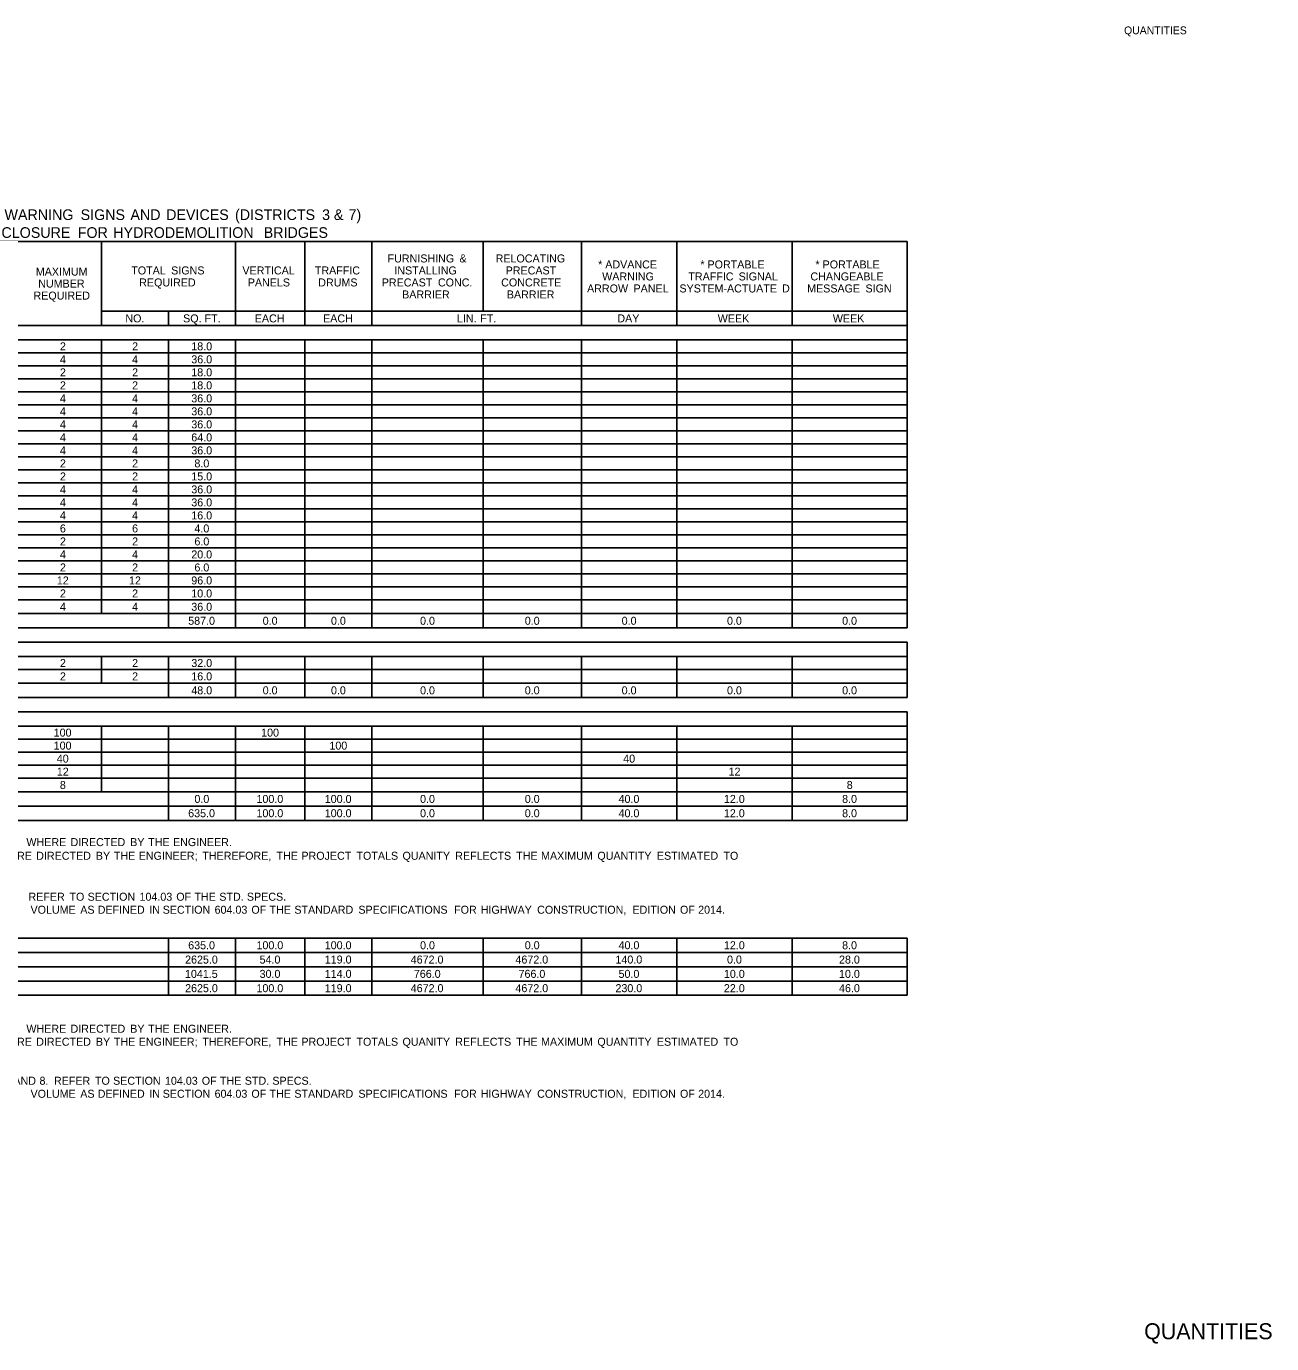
# Model space of a CAD drawing. Extents: x 540541 to 1930787, y -1948574 to 596640.
# Drawn here: x 544840 to 545774, y -1947044 to -1946056 of the extents above; entities that cross this region are included whole.
import ezdxf

# ---------------------------------------------------------------- set-up
doc = ezdxf.new("R2010")
doc.units = 0
for name, color, linetype in [('Default', 7, 'Continuous'), ('R_Border', 7, 'Continuous'), ('R_Border Prem', 7, 'Continuous')]:
    doc.layers.add(name, color=color, linetype=linetype)

msp = doc.modelspace()

# ---------------------------------------------------------------- linework, layer by layer
at = {"layer": 'Default'}
for p, q in [((544370.09, -1946217.86), (545500.6, -1946217.86)), ((544896.59, -1946280.75), (544896.59, -1946217.86)), ((544997.01, -1946280.75), (544997.01, -1946217.86)), ((545049.18, -1946280.75), (545049.18, -1946217.86)), ((545099.39, -1946280.75), (545099.39, -1946217.86)), ((545182.75, -1946270.02), (545182.75, -1946217.86)), ((545256.36, -1946280.75), (545256.36, -1946217.86)), ((545328.03, -1946280.75), (545328.03, -1946217.86)), ((545414.31, -1946280.75), (545414.31, -1946217.86)), ((545500.6, -1946270.02), (545500.6, -1946217.86)), ((544896.59, -1946270.02), (545500.6, -1946270.02)), ((544946.8, -1946280.75), (544946.8, -1946270.02)), ((545049.18, -1946280.75), (545049.18, -1946270.02)), ((545414.31, -1946280.75), (545414.31, -1946270.02)), ((545500.6, -1946291.47), (545500.6, -1946270.02)), ((544370.09, -1946280.75), (545500.6, -1946280.75)), ((544838.58, -1946280.75), (545500.6, -1946280.75)), ((544370.09, -1946291.47), (545500.6, -1946291.47)), ((544896.59, -1946496.71), (544896.59, -1946291.47)), ((544946.8, -1946496.71), (544946.8, -1946291.47)), ((544946.8, -1946507.44), (544946.8, -1946291.47)), ((544997.01, -1946507.44), (544997.01, -1946291.47)), ((544997.01, -1946507.44), (544997.01, -1946291.47)), ((545049.18, -1946486.47), (545049.18, -1946291.47)), ((545049.18, -1946507.44), (545049.18, -1946291.47)), ((545099.39, -1946507.44), (545099.39, -1946291.47)), ((545099.39, -1946507.44), (545099.39, -1946291.47)), ((545182.75, -1946507.44), (545182.75, -1946291.47)), ((545182.75, -1946507.44), (545182.75, -1946291.47)), ((545256.36, -1946507.44), (545256.36, -1946291.47)), ((545256.36, -1946507.44), (545256.36, -1946291.47)), ((545328.03, -1946507.44), (545328.03, -1946291.47)), ((545414.31, -1946507.44), (545414.31, -1946291.47)), ((545500.6, -1946496.71), (545500.6, -1946291.47)), ((544370.09, -1946301.22), (545500.6, -1946301.22)), ((544370.09, -1946310.97), (545500.6, -1946310.97)), ((544370.09, -1946320.72), (545500.6, -1946320.72)), ((544370.09, -1946330.47), (545500.6, -1946330.47)), ((544370.09, -1946340.22), (545500.6, -1946340.22)), ((544370.09, -1946349.97), (545500.6, -1946349.97)), ((544370.09, -1946359.72), (545500.6, -1946359.72)), ((544370.09, -1946369.47), (545500.6, -1946369.47)), ((544370.09, -1946379.22), (545500.6, -1946379.22)), ((544370.09, -1946388.97), (545500.6, -1946388.97)), ((544370.09, -1946398.72), (545500.6, -1946398.72)), ((544370.09, -1946408.47), (545500.6, -1946408.47)), ((544370.09, -1946418.22), (545500.6, -1946418.22)), ((544370.09, -1946427.97), (545500.6, -1946427.97)), ((544370.09, -1946437.72), (545500.6, -1946437.72)), ((544370.09, -1946447.47), (545500.6, -1946447.47)), ((544370.09, -1946457.22), (545500.6, -1946457.22)), ((544370.09, -1946466.97), (545500.6, -1946466.97)), ((544370.09, -1946476.72), (545500.6, -1946476.72)), ((544370.09, -1946486.47), (545500.6, -1946486.47)), ((544687.94, -1946496.71), (544997.01, -1946496.71)), ((544788.36, -1946496.71), (544997.01, -1946496.71)), ((544997.01, -1946496.71), (545049.18, -1946496.71)), ((545049.18, -1946496.71), (545500.6, -1946496.71)), ((545049.18, -1946507.44), (545049.18, -1946496.71)), ((545328.03, -1946507.44), (545328.03, -1946496.71)), ((545414.31, -1946507.44), (545414.31, -1946496.71)), ((545500.6, -1946507.44), (545500.6, -1946496.71)), ((544370.09, -1946507.44), (545500.6, -1946507.44)), ((544370.09, -1946518.16), (545500.6, -1946518.16)), ((544420.3, -1946518.16), (545500.6, -1946518.16)), ((545500.6, -1946528.89), (545500.6, -1946518.16)), ((544370.09, -1946528.89), (545500.6, -1946528.89)), ((544896.59, -1946548.87), (544896.59, -1946528.89)), ((544946.8, -1946548.87), (544946.8, -1946528.89)), ((544946.8, -1946559.6), (544946.8, -1946528.89)), ((544997.01, -1946548.87), (544997.01, -1946528.89)), ((544997.01, -1946559.6), (544997.01, -1946528.89)), ((545049.18, -1946559.6), (545049.18, -1946528.89)), ((545049.18, -1946559.6), (545049.18, -1946528.89)), ((545099.39, -1946559.6), (545099.39, -1946528.89)), ((545099.39, -1946559.6), (545099.39, -1946528.89)), ((545182.75, -1946559.6), (545182.75, -1946528.89)), ((545182.75, -1946559.6), (545182.75, -1946528.89)), ((545256.36, -1946559.6), (545256.36, -1946528.89)), ((545256.36, -1946559.6), (545256.36, -1946528.89)), ((545328.03, -1946559.6), (545328.03, -1946528.89)), ((545414.31, -1946559.6), (545414.31, -1946528.89)), ((545500.6, -1946559.6), (545500.6, -1946528.89)), ((544370.09, -1946538.64), (545500.6, -1946538.64)), ((544370.09, -1946548.87), (545500.6, -1946548.87)), ((544896.59, -1946548.87), (545500.6, -1946548.87)), ((545328.03, -1946559.6), (545328.03, -1946548.87)), ((544370.09, -1946559.6), (545500.6, -1946559.6)), ((544370.09, -1946570.32), (545500.6, -1946570.32)), ((545500.6, -1946651.74), (545500.6, -1946570.32)), ((544370.09, -1946581.05), (545500.6, -1946581.05)), ((544896.59, -1946630.29), (544896.59, -1946581.05)), ((544946.8, -1946651.74), (544946.8, -1946581.05)), ((544946.8, -1946651.74), (544946.8, -1946581.05)), ((544997.01, -1946651.74), (544997.01, -1946581.05)), ((544997.01, -1946651.74), (544997.01, -1946581.05)), ((545049.18, -1946651.74), (545049.18, -1946581.05)), ((545049.18, -1946651.74), (545049.18, -1946581.05)), ((545099.39, -1946651.74), (545099.39, -1946581.05)), ((545099.39, -1946651.74), (545099.39, -1946581.05)), ((545182.75, -1946651.74), (545182.75, -1946581.05)), ((545182.75, -1946651.74), (545182.75, -1946581.05)), ((545256.36, -1946651.74), (545256.36, -1946581.05)), ((545256.36, -1946651.74), (545256.36, -1946581.05)), ((545328.03, -1946651.74), (545328.03, -1946581.05)), ((545414.31, -1946651.74), (545414.31, -1946581.05)), ((544370.09, -1946590.8), (545500.6, -1946590.8)), ((544370.09, -1946600.55), (545500.6, -1946600.55)), ((544370.09, -1946610.3), (545500.6, -1946610.3)), ((544370.09, -1946620.05), (545500.6, -1946620.05)), ((544370.09, -1946630.29), (545414.31, -1946630.29)), ((544370.09, -1946630.29), (545500.6, -1946630.29)), ((545328.03, -1946651.74), (545328.03, -1946630.29)), ((545414.31, -1946630.29), (545500.6, -1946630.29)), ((544370.09, -1946641.01), (545500.6, -1946641.01)), ((544370.09, -1946651.74), (545500.6, -1946651.74)), ((544788.36, -1946739.97), (545500.6, -1946739.97)), ((544946.8, -1946739.97), (545500.6, -1946739.97)), ((544946.8, -1946782.87), (544946.8, -1946739.97)), ((544946.8, -1946782.87), (544946.8, -1946739.97)), ((544997.01, -1946782.87), (544997.01, -1946739.97)), ((545049.18, -1946772.15), (545049.18, -1946739.97)), ((545049.18, -1946782.87), (545049.18, -1946739.97)), ((545099.39, -1946750.7), (545099.39, -1946739.97)), ((545099.39, -1946782.87), (545099.39, -1946739.97)), ((545182.75, -1946750.7), (545182.75, -1946739.97)), ((545182.75, -1946782.87), (545182.75, -1946739.97)), ((545256.36, -1946750.7), (545256.36, -1946739.97)), ((545256.36, -1946782.87), (545256.36, -1946739.97)), ((545328.03, -1946750.7), (545328.03, -1946739.97)), ((545328.03, -1946782.87), (545328.03, -1946739.97)), ((545414.31, -1946782.87), (545414.31, -1946739.97)), ((545500.6, -1946782.87), (545500.6, -1946739.97)), ((544370.09, -1946750.7), (545500.6, -1946750.7)), ((544370.09, -1946761.42), (545500.6, -1946761.42)), ((544370.09, -1946772.15), (545500.6, -1946772.15)), ((544370.09, -1946782.87), (545500.6, -1946782.87))]:
    msp.add_line(p, q, dxfattribs=at)

# ---------------------------------------------------------------- texts
for s, height, p in [(' WARNING', 8, (544820.94, -1946201.63)), (' SIGNS', 8, (544878.01, -1946201.63)), (' AND', 8, (544915.35, -1946201.63)), (' DEVICES', 8, (544942.12, -1946201.63)), (' (DISTRICTS', 8, (544993.75, -1946201.63)), (' 3', 8, (545059.03, -1946201.63)), (' &', 8, (545067.86, -1946201.63)), (' 7)', 8, (545078.85, -1946201.63)), (' CLOSURE', 8, (544818.66, -1946215.04)), (' FOR', 8, (544875.86, -1946215.04)), (' HYDRODEMOLITION', 8, (544902.51, -1946215.04)), (' BRIDGES', 8, (545015.26, -1946215.04)), ('FURNISHING', 6, (545111.12, -1946233.44)), (' &', 6, (545162.78, -1946233.44)), ('RELOCATING', 6, (545192.1, -1946233.44)), ('*', 6, (545268.97, -1946237.94)), (' ADVANCE', 6, (545272.05, -1946237.94)), ('*', 6, (545345.61, -1946237.94)), (' PORTABLE', 6, (545348.7, -1946237.94)), ('*', 6, (545431.9, -1946237.94)), (' PORTABLE', 6, (545434.98, -1946237.94)), ('MAXIMUM', 6, (544847.39, -1946243.31)), ('TOTAL', 6, (544918.95, -1946242.44)), (' SIGNS', 6, (544946.64, -1946242.44)), ('VERTICAL', 6, (545002.26, -1946242.44)), ('TRAFFIC', 6, (545056.57, -1946242.44)), ('INSTALLING', 6, (545116.17, -1946242.44)), ('PRECAST', 6, (545199.61, -1946242.44)), ('WARNING', 6, (545271.96, -1946246.94)), ('TRAFFIC', 6, (545336.58, -1946246.94)), (' SIGNAL', 6, (545372.01, -1946246.94)), ('CHANGEABLE', 6, (545428.09, -1946246.94)), ('NUMBER', 6, (544849.2, -1946252.31)), ('REQUIRED', 6, (544924.88, -1946251.44)), ('PANELS', 6, (545006.29, -1946251.44)), ('DRUMS', 6, (545059.12, -1946251.44)), ('PRECAST', 6, (545106.74, -1946251.44)), (' CONC.', 6, (545146.63, -1946251.44)), ('CONCRETE', 6, (545196.24, -1946251.44)), ('ARROW', 6, (545260.65, -1946255.94)), (' PANEL', 6, (545293.24, -1946255.94)), ('SYSTEM-ACTUATE', 6, (545329.9, -1946255.94)), ('D', 6, (545406.8, -1946255.94)), ('MESSAGE', 6, (545425.62, -1946255.94)), (' SIGN', 6, (545467.14, -1946255.94)), ('REQUIRED', 6, (544845.66, -1946261.31)), ('BARRIER', 6, (545121.99, -1946260.44)), ('BARRIER', 6, (545200.48, -1946260.44)), ('NO.', 6, (544914.53, -1946278.39)), ('SQ.', 6, (544957.81, -1946278.39)), (' FT.', 6, (544971.68, -1946278.39)), ('EACH', 6, (545011.54, -1946278.39)), ('EACH', 6, (545062.73, -1946278.39)), ('LIN.', 6, (545163.09, -1946278.39)), (' FT.', 6, (545178.34, -1946278.39)), ('DAY', 6, (545283.34, -1946278.39)), ('WEEK', 6, (545358.6, -1946278.39)), ('WEEK', 6, (545444.89, -1946278.39)), ('2', 6, (544865.47, -1946299.35)), ('2', 6, (544919.59, -1946299.35)), ('18.0', 6, (544963.95, -1946299.35)), ('4', 6, (544865.46, -1946309.1)), ('4', 6, (544919.57, -1946309.1)), ('36.0', 6, (544963.95, -1946309.1)), ('2', 6, (544865.47, -1946318.85)), ('2', 6, (544919.59, -1946318.85)), ('18.0', 6, (544963.95, -1946318.85)), ('2', 6, (544865.47, -1946328.6)), ('2', 6, (544919.59, -1946328.6)), ('18.0', 6, (544963.95, -1946328.6)), ('4', 6, (544865.46, -1946338.35)), ('4', 6, (544919.57, -1946338.35)), ('36.0', 6, (544963.95, -1946338.35)), ('4', 6, (544865.46, -1946348.1)), ('4', 6, (544919.57, -1946348.1)), ('36.0', 6, (544963.95, -1946348.1)), ('4', 6, (544865.46, -1946357.85)), ('4', 6, (544919.57, -1946357.85)), ('36.0', 6, (544963.95, -1946357.85)), ('4', 6, (544865.46, -1946367.6)), ('4', 6, (544919.57, -1946367.6)), ('64.0', 6, (544963.95, -1946367.6)), ('4', 6, (544865.46, -1946377.35)), ('4', 6, (544919.57, -1946377.35)), ('36.0', 6, (544963.95, -1946377.35)), ('2', 6, (544865.47, -1946387.1)), ('2', 6, (544919.59, -1946387.1)), ('8.0', 6, (544966.28, -1946387.1)), ('2', 6, (544865.47, -1946396.85)), ('2', 6, (544919.59, -1946396.85)), ('15.0', 6, (544963.95, -1946396.85)), ('4', 6, (544865.46, -1946406.6)), ('4', 6, (544919.57, -1946406.6)), ('36.0', 6, (544963.95, -1946406.6)), ('4', 6, (544865.46, -1946416.35)), ('4', 6, (544919.57, -1946416.35)), ('36.0', 6, (544963.95, -1946416.35)), ('4', 6, (544865.46, -1946426.1)), ('4', 6, (544919.57, -1946426.1)), ('16.0', 6, (544963.95, -1946426.1)), ('6', 6, (544865.44, -1946435.85)), ('6', 6, (544919.55, -1946435.85)), ('4.0', 6, (544966.28, -1946435.85)), ('2', 6, (544865.47, -1946445.6)), ('2', 6, (544919.59, -1946445.6)), ('6.0', 6, (544966.28, -1946445.6)), ('4', 6, (544865.46, -1946455.35)), ('4', 6, (544919.57, -1946455.35)), ('20.0', 6, (544963.95, -1946455.35)), ('2', 6, (544865.47, -1946465.1)), ('2', 6, (544919.59, -1946465.1)), ('6.0', 6, (544966.28, -1946465.1)), ('12', 6, (544863.14, -1946474.85)), ('12', 6, (544917.26, -1946474.85)), ('96.0', 6, (544963.95, -1946474.85)), ('2', 6, (544865.47, -1946484.6)), ('2', 6, (544919.59, -1946484.6)), ('10.0', 6, (544963.95, -1946484.6)), ('4', 6, (544865.46, -1946494.59)), ('4', 6, (544919.57, -1946494.59)), ('36.0', 6, (544963.95, -1946494.59)), ('587.0', 6, (544961.63, -1946505.07)), ('0.0', 6, (545017.48, -1946505.07)), ('0.0', 6, (545068.66, -1946505.07)), ('0.0', 6, (545135.45, -1946505.07)), ('0.0', 6, (545213.94, -1946505.07)), ('0.0', 6, (545286.58, -1946505.07)), ('0.0', 6, (545365.55, -1946505.07)), ('0.0', 6, (545451.84, -1946505.07)), ('2', 6, (544865.47, -1946536.76)), ('2', 6, (544919.59, -1946536.76)), ('32.0', 6, (544963.95, -1946536.76)), ('2', 6, (544865.47, -1946546.76)), ('2', 6, (544919.59, -1946546.76)), ('16.0', 6, (544963.95, -1946546.76)), ('48.0', 6, (544963.96, -1946557.24)), ('0.0', 6, (545017.48, -1946557.24)), ('0.0', 6, (545068.66, -1946557.24)), ('0.0', 6, (545135.45, -1946557.24)), ('0.0', 6, (545213.94, -1946557.24)), ('0.0', 6, (545286.58, -1946557.24)), ('0.0', 6, (545365.55, -1946557.24)), ('0.0', 6, (545451.84, -1946557.24)), ('100', 6, (544860.79, -1946588.92)), ('100', 6, (545016.31, -1946588.92)), ('100', 6, (544860.79, -1946598.67)), ('100', 6, (545067.49, -1946598.67)), ('40', 6, (544863.12, -1946608.42)), ('40', 6, (545287.74, -1946608.42)), ('12', 6, (544863.14, -1946618.17)), ('12', 6, (545366.73, -1946618.17)), ('8', 6, (544865.44, -1946628.17)), ('8', 6, (545455.31, -1946628.17)), ('0.0', 6, (544966.29, -1946638.65)), ('100.0', 6, (545012.82, -1946638.65)), ('100.0', 6, (545064, -1946638.65)), ('0.0', 6, (545135.45, -1946638.65)), ('0.0', 6, (545213.94, -1946638.65)), ('40.0', 6, (545284.25, -1946638.65)), ('12.0', 6, (545363.22, -1946638.65)), ('8.0', 6, (545451.84, -1946638.65)), ('635.0', 6, (544961.63, -1946649.37)), ('100.0', 6, (545012.82, -1946649.37)), ('100.0', 6, (545064, -1946649.37)), ('0.0', 6, (545135.45, -1946649.37)), ('0.0', 6, (545213.94, -1946649.37)), ('40.0', 6, (545284.25, -1946649.37)), ('12.0', 6, (545363.22, -1946649.37)), ('8.0', 6, (545451.84, -1946649.37)), (' WHERE', 6, (544838.1, -1946671.01)), (' DIRECTED', 6, (544871.19, -1946671.01)), (' BY', 6, (544915.92, -1946671.01)), (' THE', 6, (544929.37, -1946671.01)), (' ENGINEER.', 6, (544948.02, -1946671.01)), (' WHERE', 6, (544812.37, -1946681.25)), (' DIRECTED', 6, (544845.46, -1946681.25)), (' BY', 6, (544890.19, -1946681.25)), (' THE', 6, (544903.64, -1946681.25)), (' ENGINEER;', 6, (544922.29, -1946681.25)), (' THEREFORE,', 6, (544969.99, -1946681.25)), (' THE', 6, (545025.61, -1946681.25)), (' PROJECT', 6, (545044.26, -1946681.25)), (' TOTALS', 6, (545085.55, -1946681.25)), (' QUANITY', 6, (545120.05, -1946681.25)), (' REFLECTS', 6, (545159.58, -1946681.25)), (' THE', 6, (545205.26, -1946681.25)), (' MAXIMUM', 6, (545223.91, -1946681.25)), (' QUANTITY', 6, (545266.13, -1946681.25)), (' ESTIMATED', 6, (545310.78, -1946681.25)), (' TO', 6, (545360.64, -1946681.25)), ('  REFER', 6, (544837.44, -1946711.96)), (' TO', 6, (544870.39, -1946711.96)), (' SECTION', 6, (544883.99, -1946711.96)), (' 104.03', 6, (544922.9, -1946711.96)), (' OF', 6, (544950.47, -1946711.96)), (' THE', 6, (544964.06, -1946711.96)), (' STD.', 6, (544982.71, -1946711.96)), (' SPECS.', 6, (545003.4, -1946711.96)), (' VOLUME', 6, (544841.21, -1946721.71)), (' AS', 6, (544878.49, -1946721.71)), (' DEFINED', 6, (544891.57, -1946721.71)), (' IN', 6, (544930.25, -1946721.71)), (' SECTION', 6, (544940.27, -1946721.71)), (' 604.03', 6, (544979.18, -1946721.71)), (' OF', 6, (545006.76, -1946721.71)), (' THE', 6, (545020.34, -1946721.71)), (' STANDARD', 6, (545038.99, -1946721.71)), (' SPECIFICATIONS', 6, (545086.99, -1946721.71)), (' FOR', 6, (545158.76, -1946721.71)), (' HIGHWAY', 6, (545178.67, -1946721.71)), (' CONSTRUCTION,', 6, (545220.99, -1946721.71)), (' EDITION', 6, (545292.44, -1946721.71)), (' OF', 6, (545328.08, -1946721.71)), (' 2014.', 6, (545341.67, -1946721.71)), ('635.0', 6, (544961.63, -1946748.34)), ('100.0', 6, (545012.82, -1946748.34)), ('100.0', 6, (545064, -1946748.34)), ('0.0', 6, (545135.45, -1946748.34)), ('0.0', 6, (545213.94, -1946748.34)), ('40.0', 6, (545284.25, -1946748.34)), ('12.0', 6, (545363.22, -1946748.34)), ('8.0', 6, (545451.84, -1946748.34)), ('2625.0', 6, (544959.3, -1946759.06)), ('54.0', 6, (545015.15, -1946759.06)), ('119.0', 6, (545064, -1946759.06)), ('4672.0', 6, (545128.46, -1946759.06)), ('4672.0', 6, (545206.95, -1946759.06)), ('140.0', 6, (545281.92, -1946759.06)), ('0.0', 6, (545365.55, -1946759.06)), ('28.0', 6, (545449.51, -1946759.06)), ('1041.5', 6, (544959.22, -1946769.79)), ('30.0', 6, (545015.15, -1946769.79)), ('114.0', 6, (545064, -1946769.79)), ('766.0', 6, (545130.79, -1946769.79)), ('766.0', 6, (545209.28, -1946769.79)), ('50.0', 6, (545284.25, -1946769.79)), ('10.0', 6, (545363.22, -1946769.79)), ('10.0', 6, (545449.51, -1946769.79)), ('2625.0', 6, (544959.3, -1946780.51)), ('100.0', 6, (545012.82, -1946780.51)), ('119.0', 6, (545064, -1946780.51)), ('4672.0', 6, (545128.46, -1946780.51)), ('4672.0', 6, (545206.95, -1946780.51)), ('230.0', 6, (545281.92, -1946780.51)), ('22.0', 6, (545363.22, -1946780.51)), ('46.0', 6, (545449.51, -1946780.51)), (' WHERE', 6, (544838.1, -1946810.92)), (' DIRECTED', 6, (544871.19, -1946810.92)), (' BY', 6, (544915.92, -1946810.92)), (' THE', 6, (544929.37, -1946810.92)), (' ENGINEER.', 6, (544948.02, -1946810.92)), (' WHERE', 6, (544812.37, -1946820.67)), (' DIRECTED', 6, (544845.46, -1946820.67)), (' BY', 6, (544890.19, -1946820.67)), (' THE', 6, (544903.64, -1946820.67)), (' ENGINEER;', 6, (544922.29, -1946820.67)), (' THEREFORE,', 6, (544969.99, -1946820.67)), (' THE', 6, (545025.61, -1946820.67)), (' PROJECT', 6, (545044.26, -1946820.67)), (' TOTALS', 6, (545085.55, -1946820.67)), (' QUANITY', 6, (545120.05, -1946820.67)), (' REFLECTS', 6, (545159.58, -1946820.67)), (' THE', 6, (545205.26, -1946820.67)), (' MAXIMUM', 6, (545223.91, -1946820.67)), (' QUANTITY', 6, (545266.13, -1946820.67)), (' ESTIMATED', 6, (545310.78, -1946820.67)), (' TO', 6, (545360.64, -1946820.67)), (' AND', 6, (544828.37, -1946849.92)), (' 8.', 6, (544847.95, -1946849.92)), ('  REFER', 6, (544856.54, -1946849.92)), (' TO', 6, (544889.5, -1946849.92)), (' SECTION', 6, (544903.09, -1946849.92)), (' 104.03', 6, (544942, -1946849.92)), (' OF', 6, (544969.58, -1946849.92)), (' THE', 6, (544983.16, -1946849.92)), (' STD.', 6, (545001.81, -1946849.92)), (' SPECS.', 6, (545022.51, -1946849.92)), (' VOLUME', 6, (544841.21, -1946859.67)), (' AS', 6, (544878.49, -1946859.67)), (' DEFINED', 6, (544891.57, -1946859.67)), (' IN', 6, (544930.25, -1946859.67)), (' SECTION', 6, (544940.27, -1946859.67)), (' 604.03', 6, (544979.18, -1946859.67)), (' OF', 6, (545006.76, -1946859.67)), (' THE', 6, (545020.34, -1946859.67)), (' STANDARD', 6, (545038.99, -1946859.67)), (' SPECIFICATIONS', 6, (545086.99, -1946859.67)), (' FOR', 6, (545158.76, -1946859.67)), (' HIGHWAY', 6, (545178.67, -1946859.67)), (' CONSTRUCTION,', 6, (545220.99, -1946859.67)), (' EDITION', 6, (545292.44, -1946859.67)), (' OF', 6, (545328.08, -1946859.67)), (' 2014.', 6, (545341.67, -1946859.67))]:
    msp.add_text(s, height=height, dxfattribs=at).set_placement(p)
at = {"layer": 'R_Border'}
msp.add_text('QUANTITIES', height=12, rotation=360, dxfattribs=at).set_placement((545678.28, -1947040.71))
at = {"layer": 'R_Border Prem'}
msp.add_text('QUANTITIES', height=5.862, rotation=360, dxfattribs=at).set_placement((545663.18, -1946062.39))

doc.saveas('drawing.dxf')
